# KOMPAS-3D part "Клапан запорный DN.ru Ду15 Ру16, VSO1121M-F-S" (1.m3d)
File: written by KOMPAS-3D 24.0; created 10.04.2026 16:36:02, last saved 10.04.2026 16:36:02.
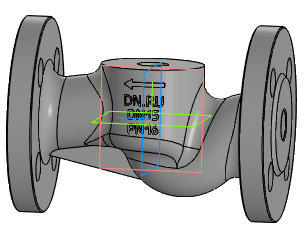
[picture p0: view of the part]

Document properties: Автор: R2D2; Полное имя файла: E:\Работа\Зайцев\VSO3131M-F-S Клапан запорный DN.ru Ду15-100 Ру16\DN15\исходные материалы\1.m3d

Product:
- Component [assembly]: Сборка  | qty 1  | pos. 1  | Автор: R2D2; source file: dn15_3d_step.a3d
- Body: Тело 1  | qty 1
    Масса: 2.310465
- Component [standard]: Фланец 15-1-01-1-B-ВЧ40-I-dв 19 ГОСТ 33259-2015  | qty 1  | Раздел спецификации: Стандартные изделия; additional columns: BOSimple***Material:38d6725a-5efe-48e1-b177-a7817acb862a
- Part/product: Клапан запорный DN.ru Ду15 Ру16  | designation VSO1121M-F-S
    Масса: 3.1
    Раздел спецификации: Прочие изделия
    Примечание: D090-01942

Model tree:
1. Эскиз:1
2. Элемент выдавливания:1  (labels: Грань.Твердое тело1)
     Расстояние 1 = 25.9988; Смещение 1 = 1
3. Эскиз:2  (with: Ребро.Элемент выдавливания:1)
4. Элемент выдавливания:2
     Расстояние 1 = 500
5. Эскиз:3
6. Элемент выдавливания:3  (with: Грань.Элемент выдавливания:1)  (labels: Грань.Твердое тело1; Твердое тело1; Solid1)
     Расстояние 1 = 500; Расстояние = 40

Referenced files in E:\Работа\Зайцев\VSO3131M-F-S Клапан запорный DN.ru Ду15-100 Ру16\DN15\исходные материалы\: dn15_3d_step.a3d
Referenced files in C:\Program Files\ASCON\KOMPAS-3D v24\Libs\PolynomLib\DATA\vault\Methods\Kompas\3D\: PLib_Flange_GOST_33259_1401.m3d
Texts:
  BOSimple***Material:38d6725a-5efe-48e1-b177-a7817acb862a
  BOSimple***PART:3f5f0d7e-d4da-47dc-6145-6a7f26b7079a***SHORTLOC:B6A6_23E38AE8DB154823[I;1;Круглый;15;1;19;0;ВЧ40 ГОСТ 7293-85]
  VSO1121M-F-S
  DN15
  GOST 26.020 Pr3
  PN16
  ВЧ40 ГОСТ 7293-85
  Ch34
  Ось Z.Начало координат
  Ось Y.Начало координат
  Плоскость ZX.Начало координат
  Plane ZX. Origin
  Плоскость ZY.Начало координат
